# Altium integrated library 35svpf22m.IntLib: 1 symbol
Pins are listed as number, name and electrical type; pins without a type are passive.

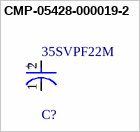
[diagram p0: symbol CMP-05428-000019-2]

## CMP-05428-000019-2
designator C?, comment 35SVPF22M
Conductive Polymer Aluminum Solid Capacitors (OS-CON) 22uF ±20% 35V; Ripple Current (AC): 2.6A; ESR (Equivalent Series Resistance): 35mR; Leakage Current: 154uA; Life (Hours): 5000Hour; Polarity: Polar; Dissipation Factor: 12%
footprint FP-OS-CON-SMT-C6-MFG
pins: 1 C, 2 A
